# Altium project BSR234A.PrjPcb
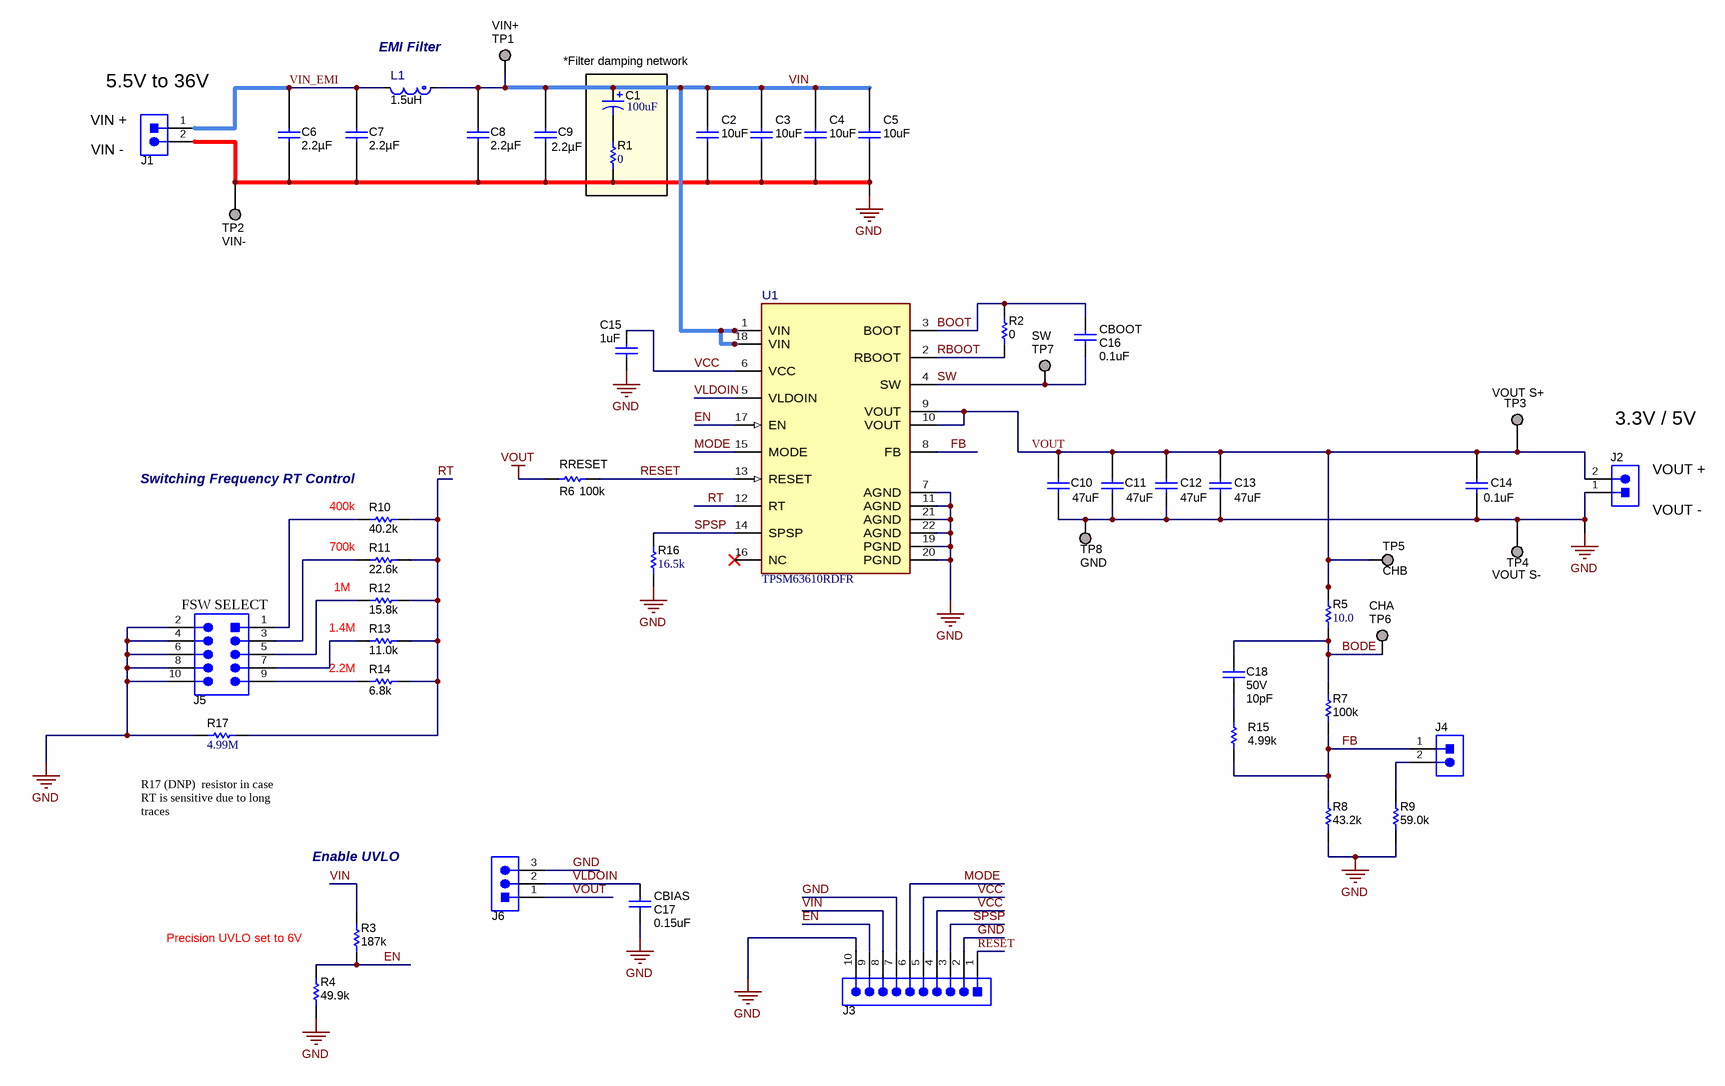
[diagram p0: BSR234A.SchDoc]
CopyrightYear: 2022; PCB_Layout: Jimmy Hua; PCB_Rev: A; PRJ_Customer: Public Release; PRJ_Engineer: Jimmy Hua; PRJ_Number: BSR234; PRJ_Title: VeyronModuleEVM; SCH_Rev: A; TechSupport: http://www.ti.com/support; TID: N/A
2 sheets, 91 parts. Net scope: global (net labels, ports and power ports of the same name join across sheets).
Board file: BSR234A.PcbDoc
Sheets:
  BSR234A.SchDoc
  BSR234A_Hardware.SchDoc

## Sheet BSR234A.SchDoc: TPSM63610 schematic
size 431 x 279 mm; REV: A; Date: Not shown in title block; ApprovedBy: Not shown in title block; CheckedBy: Not shown in title block; Author: Not shown in title block; CompanyName: Not shown in title block; DrawnBy: Jimmy Hua; Engineer: Jimmy Hua; Organization: Not shown in title block; Address1: Not shown in title block; Address2: Not shown in title block; Address3: Not shown in title block; Address4: Not shown in title block; DocumentNumber: 1; Revision: Use project parameter SCH_Rev; SheetNumber: 2; SheetTotal: 2; PageSetup: Record=PageOptions¦CenterHorizontal=True¦CenterVertical=True¦PrintScale=1.00¦XCorrection=1.00¦YCorrection=1.00¦PrintKind=0¦BorderSize=5000000¦LeftOffset=0¦BottomOffset=0¦Orientation=2¦PaperLength=1000¦PaperWidth=1000¦Scale=100¦PaperSource=15¦PrintQuality=600¦MediaType=1¦DitherType=10¦PaperKind=Letter¦PrintScaleMode=1

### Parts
C1  ValueDisplayed: 100uF  [SM_RADIAL_8MM]  (hidden comment: UUD1H101MNL1GS)
C2  ValueDisplayed: 10uF  [1210_270L]  (hidden comment: GRM32ER71H106KA12L)
C3  ValueDisplayed: 10uF  [1210_270L]  (hidden comment: GRM32ER71H106KA12L)
C4  ValueDisplayed: 10uF  [1210_270L]  (hidden comment: GRM32ER71H106KA12L)
C5  ValueDisplayed: 10uF  [1210_270L]  (hidden comment: GRM32ER71H106KA12L)
C6  Cap_F: 2.2µF  [0805L]  (hidden comment: CGA4J3X7R1H225K125AB)
C7  Cap_F: 2.2µF  [0805L]  (hidden comment: CGA4J3X7R1H225K125AB)
C8  Cap_F: 2.2µF  [0805L]  (hidden comment: CGA4J3X7R1H225K125AB)
C9  Cap_F: 2.2µF  [0805L]  (hidden comment: CGA4J3X7R1H225K125AB)
C10  ValueDisplayed: 47uF  [1210_270L]  (hidden comment: GRM32EC81C476ME15L)
C11  ValueDisplayed: 47uF  [1210_270L]  (hidden comment: GRM32EC81C476ME15L)
C12  ValueDisplayed: 47uF  [1210_270L]  (hidden comment: GRM32EC81C476ME15L)
C13  ValueDisplayed: 47uF  [1210_270L]  (hidden comment: GRM32EC81C476ME15L)
C14  ValueDisplayed: 0.1uF  [0603L]  (hidden comment: CGA3E2X7R1E104K080AA)
C15  ValueDisplayed: 1uF  [0603L]  (hidden comment: Capacitor)
C16  CBOOT  ValueDisplayed: 0.1uF  [0402S]
C17  CBIAS  ValueDisplayed: 0.15uF  [0603S]
C18  VDC_V: 50V  ValueDisplayed: 10pF  [0402L]  (hidden comment: CGA2B2C0G1H100D050BA)
J1  1729018  [Phoenix_1729018]  (value not drawn)
J2  1729018  [Phoenix_1729018]  (value not drawn)
J3  TSW-110-07-G-S  [TSW-110-07-G-S]  (value not drawn)
J4  PBC02SAAN  [Sullins_PBC02SAAN]  (value not drawn)
J5  PEC05DAAN  [CONN_PEC05DAAN]  (value not drawn)
J6  PBC03SAAN  [PBC03SAAN]  (value not drawn)
L1  value 1.5uH  [FP-XGL4030-152MEC_SMT2_4MM0_4MM0-MFG]  (hidden comment: XGL4030-152MEC)
R1  ValueDisplayed: 0  [0603L]  (hidden comment: CRCW06030000Z0EA)
R2  ValueDisplayed: 0  [0402S]  (hidden comment: CRCW04020000Z0EDHP)
R3  ValueDisplayed: 187k  [0603]  (hidden comment: CRCW0603187KFKEA)
R4  ValueDisplayed: 49.9k  [0603]  (hidden comment: CRCW060349K9FKEA)
R5  ValueDisplayed: 10.0  [0402L]  (hidden comment: CRCW040210R0FKED)
R6  RRESET  ValueDisplayed: 100k  [0603S]
R7  ValueDisplayed: 100k  [0402S]  (hidden comment: RFBT)
R8  ValueDisplayed: 43.2k  [0402S]  (hidden comment: RFBB)
R9  ValueDisplayed: 59.0k  [0402S]  (hidden comment: RFBB5V)
R10  ValueDisplayed: 40.2k  [0402]  (hidden comment: CRCW040240K2FKED)
R11  ValueDisplayed: 22.6k  [0402]  (hidden comment: CRCW040222K6FKED)
R12  ValueDisplayed: 15.8k  [0402]  (hidden comment: CRCW040215K8FKED)
R13  ValueDisplayed: 11.0k  [0402]  (hidden comment: CRCW040211K0FKED)
R14  ValueDisplayed: 6.8k  [0402]  (hidden comment: CRCW04026K80JNED)
R15  ValueDisplayed: 4.99k  [0402L]  (hidden comment: CRCW04024K99FKED)
R16  ValueDisplayed: 16.5k  [0603S]  (hidden comment: CRCW060316K5FKEA)
R17  ValueDisplayed: 4.99M  [0603]  (hidden comment: CRCW06034M99FKEA)
TP1  VIN+  [Keystone_5019]
TP2  VIN-  [Keystone_5019]
TP3  5019  [Keystone_5019]  (value not drawn)
TP4  5019  [Keystone_5019]  (value not drawn)
TP5  CHB  [Keystone_5019]
TP6  CHA  [Keystone_5019]
TP7  SW  [Keystone_5019]
TP8  GND  [Keystone_5019]
U1  TPSM63610RDFR  [RDF0022A-MFG]

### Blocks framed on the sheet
*Filter damping network: C1 R1

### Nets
GND: C2.1 C3.1 C4.1 C5.1 C6.2 C7.2 C8.2 C9.2 C10.1 C11.1 C12.2 C13.2 C14.2 C15.2 C17.1 J1.2 J2.1 J3.2 J3.7 J3.10 J5.2 J5.4 J5.6 J5.8 J5.10 J6.3 R1.1 R4.1 R8.1 R9.1 R16.1 R17.1 TP2.1 TP4.1 TP8.1 U1.7(AGND) U1.11(AGND) U1.19(PGND) U1.20(PGND) U1.21(AGND) U1.22(AGND)
VOUT: C10.2 C11.2 C12.1 C13.1 C14.1 J2.2 J6.1 R5.2 R6.2 TP3.1 TP5.1 U1.9(VOUT) U1.10(VOUT)
BODE: C18.1 R5.1 R7.2 TP6.1
BOOT: C16.2 R2.2 U1.3(BOOT)
EN: J3.9 R3.2 R4.2 U1.17(EN)
FB: J4.1 R7.1 R8.2 R15.1 U1.8(FB)
MODE: J3.6 U1.15(MODE)
RBOOT: R2.1 U1.2(RBOOT)
RESET: J3.1 R6.1 U1.13(RESET)
RT: R10.2 R11.2 R12.2 R13.2 R14.2 R17.2 U1.12(RT)
SPSP: J3.3 R16.2 U1.14(SPSP)
SW: C16.1 TP7.1 U1.4(SW)
VCC: C15.1 J3.4 J3.5 U1.6(VCC)
VIN: C1.1(+) C2.2 C3.2 C4.2 C5.2 C8.1 C9.1 J3.8 L1.1 R3.1 TP1.1 U1.1(VIN) U1.18(VIN)
VIN_EMI: C6.1 C7.1 J1.1 L1.2
VLDOIN: C17.2 J6.2 U1.5(VLDOIN)
NetC1_2: C1.2(-) R1.2
NetC18_2: C18.2 R15.2
NetJ4_2: J4.2 R9.2
NetJ5_1: J5.1 R10.1
NetJ5_3: J5.3 R11.1
NetJ5_5: J5.5 R12.1
NetJ5_7: J5.7 R13.1
NetJ5_9: J5.9 R14.1

Not connected (* = marked no-connect by the designer): U1 16(NC)*

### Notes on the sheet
- (near J1) 5.5V to 36V
- (near L1) EMI Filter
- (near J1) VIN -
- (near J1) VIN +
- (near TP3) VOUT S+
- (near J2) 3.3V / 5V
- (near R10) Switching Frequency RT Control
- (near R10) 400k
- (near J2) VOUT +
- 700k
- (near TP4) VOUT S-
- (near J2) VOUT -
- (near J5) FSW SELECT
- 1.4M
- 1M
- 2.2M
- (near R17) R17 (DNP)  resistor in case RT is sensitive due to long traces
- Enable UVLO
- Precision UVLO set to 6V

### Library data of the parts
C1 = CMP-0011414-2: CAP, AL, 100 uF, 50 V, +/- 20%, 0.34 ohm, SMD; Manufacturer: Nichicon; TaMin_C: -55°C; ESR_ohm: 0.34; Polarized: Y; SizeAreaWB_mm2: 113.3; U/M: EA; Value: 100uF; TaMax_C: 105°C; SizeZ_mm: 10.2; SizeX_mm: 9; SizeY_mm: 8.3; Cap_Case: 8x10; Value2: 50V; SizeArea_mm2: 74.7; CompType: Capacitor; Cap_F: 100µF; IRMS_A: 300mA; AEC Category: Q200
C2-C5 = CMP-0009226-3: CAP, CERM, 10 uF, 50 V, +/- 10%, X7R, 1210; Manufacturer: MuRata; TaMin_C: -55°C; Polarized: N; SizeAreaWB_mm2: 14.7; Value1: Unknown; U/M: EA; Value: 10uF; TaMax_C: 125°C; SizeZ_mm: 2.7; SizeX_mm: 3.2; SizeY_mm: 2.5; Cap_Case: 1210; Value2: 50V; SizeArea_mm2: 8; Cap_F: 10µF; AEC Category: Q200
C6-C9 = CMP-0007977-2: CAP, CERM, 2.2 uF, 50 V, +/- 10%, X7R, AEC-Q200 Grade 1, 0805; Manufacturer: TDK; TaMin_C: -55°C; ESR_ohm: 3.288m; Polarized: N; SizeAreaWB_mm2: 6.75; Value1: 0.003288 ohm; U/M: EA; Value: 2.2uF; TaMax_C: 125°C; SizeZ_mm: 1.45; SizeX_mm: 2; SizeY_mm: 1.25; Cap_Case: 0805; Value2: 50V; SizeArea_mm2: 2.5; AEC Qualified: Y; IRMS_A: 3.60029A; AEC Grade: 1; AEC Category: Q200
C10-C13 = CMP-0009201-2: CAP, CERM, 47 uF, 16 V, +/- 20%, X6S, 1210; Manufacturer: MuRata; TaMin_C: -55°C; Polarized: N; SizeAreaWB_mm2: 14.7; Value1: Unknown; U/M: EA; Value: 47uF; TaMax_C: 105°C; SizeZ_mm: 2.7; SizeX_mm: 3.2; SizeY_mm: 2.5; Cap_Case: 1210; Value2: 16V; SizeArea_mm2: 8; Cap_F: 47µF; AEC Category: Q200
C14 = CMP-0007077-5: CAP, CERM, 0.1 uF, 25 V, +/- 10%, X7R, AEC-Q200 Grade 1, 0603; Manufacturer: TDK; TaMin_C: -55°C; Polarized: N; SizeAreaWB_mm2: 4.68; Value1: Unknown; U/M: EA; Value: 0.1uF; TaMax_C: 125°C; SizeZ_mm: 1; SizeX_mm: 1.6; SizeY_mm: 0.8; Cap_Case: 0603; Value2: 25V; SizeArea_mm2: 1.28; AEC Qualified: Y; Cap_F: 100nF; AEC Category: Q200
C15 = CMP-0006867-4: CAP, CERM, 1 uF, 25 V, +/- 10%, X7R, 0603; PartNumber: C0603C105K3RACTU; Manufacturer: Kemet; Polarized: N; Value: 1uF; U/M: EA; Cap_F: 1µF; Value1: Unknown; VDC_V: 25V; TaMin_C: -55°C; TaMax_C: 125°C; Cap_Case: 0603; AEC Category: Q200; SizeArea_mm2: 1.28; SizeAreaWB_mm2: 4.68; SizeX_mm: 1.6; SizeY_mm: 0.8; SizeZ_mm: 1
C16 = CMP-0006325-2: CAP, CERM, 0.1 uF, 50 V, +/- 10%, X7R, AEC-Q200 Grade 1, 0402; Manufacturer: TDK; PartNumber: CGA2B3X7R1H104K050BB; TaMin_C: -55°C; ESR_ohm: 0.039064; Polarized: N; SizeAreaWB_mm2: 3; Value1: 0.039064 ohm; U/M: EA; Value: 0.1uF; TaMax_C: 125°C; SizeZ_mm: 0.6; SizeX_mm: 1; SizeY_mm: 0.5; Cap_Case: 0402; Value2: 50V; CompType: Capacitor; AEC Qualified: Y; Cap_F: 100nF; IRMS_A: 8.14669dA; AEC Category: Q200
C17 = CMP-0007093-5: CAP, CERM, 0.15 uF, 50 V, +/- 10%, X7R, AEC-Q200 Grade 1, 0603; Manufacturer: TDK; PartNumber: CGA3E3X7R1H154K080AB; TaMin_C: -55°C; ESR_ohm: 0.028863; Polarized: N; SizeAreaWB_mm2: 4.68; Value1: 0.028863 ohm; U/M: EA; Value: 0.15uF; TaMax_C: 125°C; SizeZ_mm: 1; SizeX_mm: 1.6; SizeY_mm: 0.8; Cap_Case: 0603; Value2: 50V; SizeArea_mm2: 1.28; CompType: Capacitor; AEC Qualified: Y; Cap_F: 150nF; IRMS_A: 9.78809dA; AEC Category: Q200
C18 = CMP-0006307-2: CAP, CERM, 10 pF, 50 V, +/- 5%, C0G/NP0, AEC-Q200 Grade 1, 0402; Manufacturer: TDK; TaMin_C: -55°C; Polarized: N; SizeAreaWB_mm2: 3; Value1: Unknown; U/M: EA; Value: 10pF; TaMax_C: 125°C; SizeZ_mm: 0.6; SizeX_mm: 1; SizeY_mm: 0.5; Cap_Case: 0402; CompType: Capacitor; AEC Qualified: Y; AEC Category: Q200
J1 J2 = CMP-0055486-1: TERM BLOCK 2POS 5mm, TH; Manufacturer: Phoenix Contact; CT: TRUE; Green_REACh: Incomplete; CompType: Terminal Block; CNHeader: FALSE; Green_Lifecycle: Not Set
J3 = CMP-0075422-1: Header, 100mil, 10x1, Gold, TH; Manufacturer: Samtec; Pitch_mm: 2.54; Cert_VDE: N; Gender: Male; Cert_CSA: Y; Voltage_V: 550V; Green_REACh: Passed; Current_A: 6.3A; CT: False; Green_Lifecycle: Active; Row_Count: 1; CNHeader: True
J4 = CMP-0054566-1: Header, 100mil, 2x1, Gold, TH; Manufacturer: Sullins Connector Solutions; CNHeader: TRUE; Current_A: 3A; Green_Lifecycle: Active; Shrouded: N; Gender: Male; Green_REACh: Passed; Voltage_V: 1.8kV; Row_Count: 1; Pitch_mm: 2.54; CT: FALSE; Cert_UL: Y
J5 = CMP-0054550-2: Header, 100mil, 5x2, Tin, TH; Manufacturer: Sullins Connector Solutions; Pitch_mm: 2.54; Gender: Male; Cert_UL: Y; Voltage_V: 1.8kV; Green_REACh: Passed; Current_A: 3A; Shrouded: N; Green_Lifecycle: Active; Row_Count: 2
J6 = CMP-0002334-1: Header, 100mil, 3x1, Gold, TH; Manufacturer: Sullins Connector Solutions; CNHeader: TRUE; CT: FALSE; Green_Lifecycle: Not Set; Green_REACh: Incomplete
L1 = CMP-0092596-1: Shielded Power Inductors 1.5 µH 10.2A 10.5mOhm Max Nonstandard; Manufacturer: Coilcraft; Isat: 3.8A; Tolerance_%: 20%; AEC Grade: Grade 1; Self Resonant Frequency: 50MHz; TaMin_C: -40°C; Test Frequency: 1MHz; Material: Composite; DCR_ohm: 0.0105; TaMax_C: +125°C; AEC Qualified: Yes; SizeZ_mm: 3.1mm; Ind_H: 1.5µH; Shrouded: true
R1 = CMP-0025697-4: RES, 0, 5%, 0.1 W, AEC-Q200 Grade 0, 0603; Manufacturer: Vishay-Dale; Power_W: 100mW; TempCo: 200 ppm/C; Value_Code: 0000; Value: 0; EIA_Code: E24; SizeX_mm: 1.6; SizeY_mm: 0.8; SizeZ_mm: 1; Value2: 0.1W; SizeArea_mm2: 1.28; AEC Qualified: Y; VDC_V: 75V; AEC Category: Q200
R2 = CMP-0081856-1: RES, 0, 0%, 0.2 W, AEC-Q200 Grade 0, 0402; Manufacturer: Vishay-Dale; SizeAreaWB_mm2: 3; SizeArea_mm2: 0.5; AEC Qualified: Y; AEC Category: Q200; Value: 0; SizeZ_mm: 0.6; Power_W: 200mW; VDC_V: 50V; Value2: 0.2W; SizeX_mm: 1
R3 = CMP-0022095-4: RES, 187 k, 1%, 0.1 W, AEC-Q200 Grade 0, 0603; Manufacturer: Vishay-Dale; Power_W: 100mW; TempCo: 100 ppm/C; Value: 187k; EIA_Code: E96; SizeX_mm: 1.6; SizeY_mm: 0.8; SizeZ_mm: 1; Value2: 0.1W; SizeArea_mm2: 1.28; AEC Qualified: Y; VDC_V: 75V; AEC Category: Q200; AEC Grade: 0
R4 = CMP-0022447-4: RES, 49.9 k, 1%, 0.1 W, AEC-Q200 Grade 0, 0603; Manufacturer: Vishay-Dale; Power_W: 100mW; TempCo: 100 ppm/C; Value_Code: 49k9; Value: 49.9k; EIA_Code: E96; SizeX_mm: 1.6; SizeY_mm: 0.8; SizeZ_mm: 1; Value2: 0.1W; SizeArea_mm2: 1.28; AEC Qualified: Y; VDC_V: 75V; AEC Category: Q200; AEC Grade: 0
R5 = CMP-0025963-1: RES, 10.0, 1%, 0.063 W, 0402; Manufacturer: Vishay-Dale; Power_W: 63mW; TempCo: 100 ppm/C; Value_Code: 10R0; U/M: EA; Value: 10.0; EIA_Code: E96; Res_ohm: 10; SizeX_mm: 1; SizeY_mm: 0.5; SizeZ_mm: 0.6; Value2: 0.063W; VDC_V: 50V; AEC Category: Q200
R6 = CMP-0021990-4: RES, 100 k, 1%, 0.1 W, AEC-Q200 Grade 0, 0603; Manufacturer: Vishay-Dale; PartNumber: CRCW0603100KFKEA; Power_W: 100mW; TempCo: 100 ppm/C; Value: 100k; EIA_Code: E96; SizeX_mm: 1.6; SizeY_mm: 0.8; SizeZ_mm: 1; Value2: 0.1W; SizeArea_mm2: 1.28; CompType: Resistor; AEC Qualified: Y; VDC_V: 75V; AEC Category: Q200; AEC Grade: 0
R7 = CMP-0025950-3: RES, 100 k, 1%, 0.063 W, AEC-Q200 Grade 0, 0402; Manufacturer: Vishay-Dale; PartNumber: CRCW0402100KFKED; Power_W: 63mW; TempCo: 100 ppm/C; Value: 100k; EIA_Code: E96; SizeX_mm: 1; SizeY_mm: 0.5; SizeZ_mm: 0.6; Value2: 0.063W; CompType: Resistor; AEC Qualified: Y; VDC_V: 50V; AEC Category: Q200; AEC Grade: 0
R8 = CMP-0026379-2: RES, 43.2 k, 1%, 0.063 W, AEC-Q200 Grade 0, 0402; Manufacturer: Vishay-Dale; PartNumber: CRCW040243K2FKED; Power_W: 63mW; TempCo: 100 ppm/C; Value_Code: 43k2; Value: 43.2k; EIA_Code: E96; SizeX_mm: 1; SizeY_mm: 0.5; SizeZ_mm: 0.6; Value2: 0.063W; CompType: Resistor; AEC Qualified: Y; VDC_V: 50V; AEC Category: Q200; AEC Grade: 0
R9 = CMP-0026461-2: RES, 59.0 k, 1%, 0.063 W, AEC-Q200 Grade 0, 0402; Manufacturer: Vishay-Dale; PartNumber: CRCW040259K0FKED; Power_W: 63mW; TempCo: 100 ppm/C; Value_Code: 59k0; Value: 59.0k; EIA_Code: E96; Res_ohm: 59k; SizeX_mm: 1; SizeY_mm: 0.5; SizeZ_mm: 0.6; Value2: 0.063W; CompType: Resistor; AEC Qualified: Y; VDC_V: 50V; AEC Category: Q200; AEC Grade: 0
R10 = CMP-0026367-2: RES, 40.2 k, 1%, 0.063 W, AEC-Q200 Grade 0, 0402; Manufacturer: Vishay-Dale; Power_W: 63mW; TempCo: 100 ppm/C; Value_Code: 40k2; Value: 40.2k; EIA_Code: E96; SizeX_mm: 1; SizeY_mm: 0.5; SizeZ_mm: 0.6; Value2: 0.063W; AEC Qualified: Y; VDC_V: 50V; AEC Category: Q200; AEC Grade: 0
R11 = CMP-0026179-2: RES, 22.6 k, 1%, 0.063 W, AEC-Q200 Grade 0, 0402; Manufacturer: Vishay-Dale; Power_W: 63mW; TempCo: 100 ppm/C; Value_Code: 22k6; Value: 22.6k; EIA_Code: E96; SizeX_mm: 1; SizeY_mm: 0.5; SizeZ_mm: 0.6; Value2: 0.063W; AEC Qualified: Y; VDC_V: 50V; AEC Category: Q200; AEC Grade: 0
R12 = CMP-0026029-3: RES, 15.8 k, 1%, 0.063 W, AEC-Q200 Grade 0, 0402; Manufacturer: Vishay-Dale; Power_W: 63mW; TempCo: 100 ppm/C; Value_Code: 15k8; Value: 15.8k; EIA_Code: E96; SizeX_mm: 1; SizeY_mm: 0.5; SizeZ_mm: 0.6; Value2: 0.063W; AEC Qualified: Y; VDC_V: 50V; AEC Category: Q200; AEC Grade: 0
R13 = CMP-0025975-2: RES, 11.0 k, 1%, 0.063 W, 0402; Manufacturer: Vishay-Dale; Power_W: 63mW; TempCo: 100 ppm/C; Value_Code: 11k0; U/M: EA; Value: 11.0k; EIA_Code: E96; Res_ohm: 11k; SizeX_mm: 1; SizeY_mm: 0.5; SizeZ_mm: 0.6; Value2: 0.063W; VDC_V: 50V; AEC Category: Q200
R14 = CMP-0026966-5: RES, 6.8 k, 5%, 0.063 W, AEC-Q200 Grade 0, 0402; Manufacturer: Vishay-Dale; Power_W: 63mW; TempCo: 200 ppm/C; Value_Code: 6k80; Value: 6.8k; EIA_Code: E24; SizeX_mm: 1; SizeY_mm: 0.5; SizeZ_mm: 0.6; Value2: 0.063W; AEC Qualified: Y; VDC_V: 50V; AEC Category: Q200; AEC Grade: 0
R15 = CMP-0026414-2: RES, 4.99 k, 1%, 0.063 W, AEC-Q200 Grade 0, 0402; Manufacturer: Vishay-Dale; Power_W: 63mW; TempCo: 100 ppm/C; Value_Code: 4k99; Value: 4.99k; EIA_Code: E96; SizeX_mm: 1; SizeY_mm: 0.5; SizeZ_mm: 0.6; Value2: 0.063W; CompType: Resistor; AEC Qualified: Y; VDC_V: 50V; AEC Category: Q200; AEC Grade: 0
R16 = CMP-0022080-4: RES, 16.5 k, 1%, 0.1 W, AEC-Q200 Grade 0, 0603; Manufacturer: Vishay-Dale; Power_W: 100mW; TempCo: 100 ppm/C; Value_Code: 16k5; Value: 16.5k; EIA_Code: E96; SizeX_mm: 1.6; SizeY_mm: 0.8; SizeZ_mm: 1; Value2: 0.1W; SizeArea_mm2: 1.28; AEC Qualified: Y; VDC_V: 75V; AEC Category: Q200; AEC Grade: 0
R17 = CMP-0022468-4: RES, 4.99 M, 1%, 0.1 W, AEC-Q200 Grade 0, 0603; Manufacturer: Vishay-Dale; Power_W: 100mW; TempCo: 100 ppm/C; Value_Code: 4M99; Value: 4.99Meg; EIA_Code: E96; SizeX_mm: 1.6; SizeY_mm: 0.8; SizeZ_mm: 1; Value2: 0.1W; SizeArea_mm2: 1.28; AEC Qualified: Y; VDC_V: 75V; AEC Category: Q200; AEC Grade: 0
TP1 TP2 TP5-TP8 = CMP-0055162-1: Test Point, Miniature, SMT; Manufacturer: Keystone; PartNumber: 5019; CNHeader: FALSE; Green_Lifecycle: Active; Green_REACh: Passed; CT: TRUE
TP3 TP4 = CMP-0055162-1: Test Point, Miniature, SMT; Manufacturer: Keystone; CNHeader: FALSE; Green_Lifecycle: Active; Green_REACh: Passed; CT: TRUE
U1 = CMP-0095755-2: Manufacturer: Texas Instruments; CompType: IC; AEC Category: Q200; SizeZ_mm: 4.05mm

## Sheet BSR234A_Hardware.SchDoc: TPSM63610
size 431 x 279 mm; Date: Not shown in title block; ApprovedBy: Not shown in title block; CheckedBy: Not shown in title block; Author: Not shown in title block; CompanyName: Not shown in title block; DrawnBy: Jimmy Hua; Engineer: Not shown in title block; Organization: Not shown in title block; Address1: Not shown in title block; Address2: Not shown in title block; Address3: Not shown in title block; Address4: Not shown in title block; DocumentNumber: 1; Revision: Use project parameter SCH_Rev; SheetNumber: 1; SheetTotal: 2; PageSetup: Record=PageOptions¦CenterHorizontal=True¦CenterVertical=True¦PrintScale=1.00¦XCorrection=1.00¦YCorrection=1.00¦PrintKind=0¦BorderSize=5000000¦LeftOffset=0¦BottomOffset=0¦Orientation=2¦PaperLength=1000¦PaperWidth=1000¦Scale=100¦PaperSource=15¦PrintQuality=600¦MediaType=1¦DitherType=10¦PaperKind=Letter¦PrintScaleMode=1
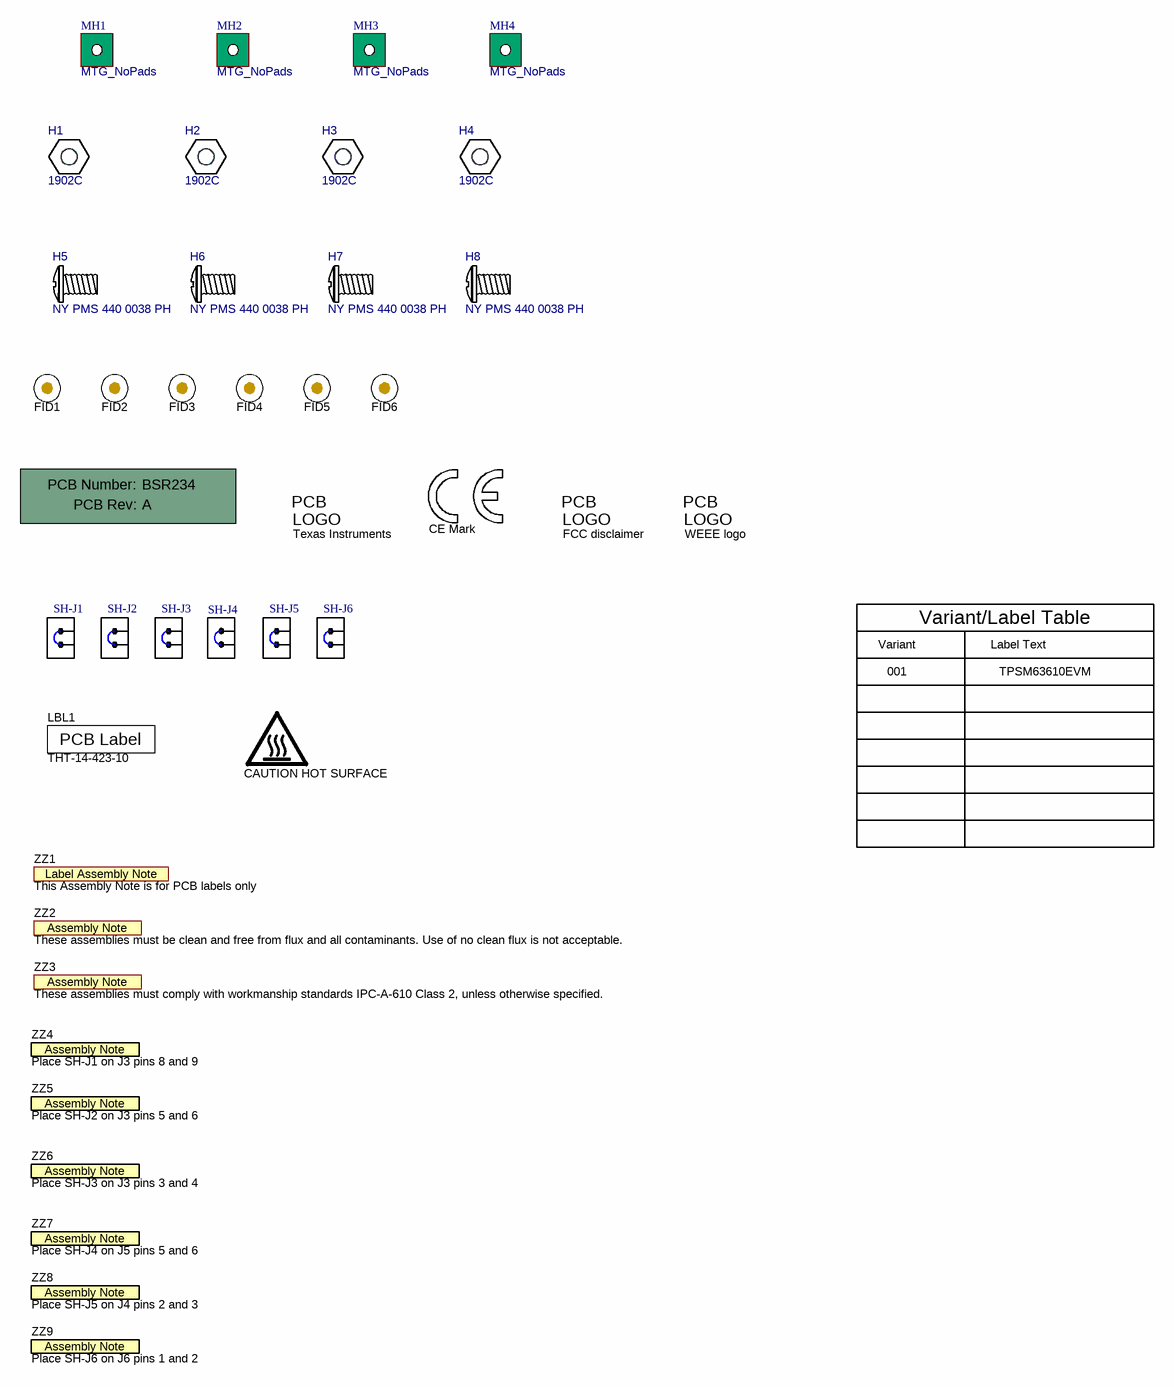
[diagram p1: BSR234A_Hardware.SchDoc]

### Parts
!PCB1  Printed Circuit Board  (value not drawn)  (mechanical)
FID1  Fiducial  [Fiducial10-20]  (value not drawn)
FID2  Fiducial  [Fiducial10-20]  (value not drawn)
FID3  Fiducial  [Fiducial10-20]  (value not drawn)
FID4  Fiducial  [Fiducial10-20]  (value not drawn)
FID5  Fiducial  [Fiducial10-20]  (value not drawn)
FID6  Fiducial  [Fiducial10-20]  (value not drawn)
H1  1902C  [Keystone_1902C]  (mechanical)
H2  1902C  [Keystone_1902C]  (mechanical)
H3  1902C  [Keystone_1902C]  (mechanical)
H4  1902C  [Keystone_1902C]  (mechanical)
H5  NY PMS 440 0038 PH  (mechanical)
H6  NY PMS 440 0038 PH  (mechanical)
H7  NY PMS 440 0038 PH  (mechanical)
H8  NY PMS 440 0038 PH  (mechanical)
LBL1  THT-14-423-10  [Label_650x200]
Logo1  CE Mark  [CE_Mark_5mm]  (no BOM)
Logo2  Texas Instruments  [TI_Stacked_Overlay_Small]  (no BOM)
Logo3  FCC disclaimer  [FCC_disclaimer]  (no BOM)
Logo4  WEEE logo  [WEEE_Minimum]  (no BOM)
LOGO5  CAUTION HOT SURFACE  [IEC_HotSurface_Small]  (no BOM)
MH1  MTG_NoPads  [MTG_159mil]  (no BOM)
MH2  MTG_NoPads  [MTG_159mil]  (no BOM)
MH3  MTG_NoPads  [MTG_159mil]  (no BOM)
MH4  MTG_NoPads  [MTG_159mil]  (no BOM)
SH-J1  SNT-100-BK-G  [SNT-100-BK-G]  (value not drawn)
SH-J2  SNT-100-BK-G  [SNT-100-BK-G]  (value not drawn)
SH-J3  SNT-100-BK-G  [SNT-100-BK-G]  (value not drawn)
SH-J4  SNT-100-BK-G  [SNT-100-BK-G]  (value not drawn)
SH-J5  SNT-100-BK-G  [SNT-100-BK-G]  (value not drawn)
SH-J6  SNT-100-BK-G  [SNT-100-BK-G]  (value not drawn)
ZZ1  This Assembly Note is for PCB labels only  [AssemblyNoteLabel]  (no BOM)
ZZ2  These assemblies must be clean and free from flux and all contaminants. Use of no clean flux is not acceptable.  [AssemblyNote]  (no BOM)
ZZ3  These assemblies must comply with workmanship standards IPC-A-610 Class 2, unless otherwise specified.  [AssemblyNote]  (no BOM)
ZZ4  Place SH-J1 on J3 pins 8 and 9  [AssemblyNote]  (no BOM)
ZZ5  Place SH-J2 on J3 pins 5 and 6  [AssemblyNote]  (no BOM)
ZZ6  Place SH-J3 on J3 pins 3 and 4  [AssemblyNote]  (no BOM)
ZZ7  Place SH-J4 on J5 pins 5 and 6  [AssemblyNote]  (no BOM)
ZZ8  Place SH-J5 on J4 pins 2 and 3  [AssemblyNote]  (no BOM)
ZZ9  Place SH-J6 on J6 pins 1 and 2  [AssemblyNote]  (no BOM)

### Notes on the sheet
- Variant/Label Table
- Variant
- 001
- Label Text
- TPSM63610EVM

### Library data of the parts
!PCB1 = CMP-0003618-2: Manufacturer: Any; PartNumber: BSR234
FID1-FID6 = CMP-0077181-1: Fiducial mark.  There is nothing to buy or mount.
H1-H4 = CMP-0003610-1: Standoff, Hex, 0.5"L #4-40 Nylon; Manufacturer: Keystone; CompType: Hardware
H5-H8 = CMP-0003667-1: Screw, Pan Head , 4-40, 3/8", Nylon; Manufacturer: B&F Fastener Supply; CompType: Hardware
LBL1 = CMP-0003625-1: Manufacturer: Brady
Logo1 = CMP-0074844-1: SymbolCreator: a0412235
Logo2 = CMP-0074838-1: Texas Instrument Corporate Signature; SymbolCreator: a0412235; Lib Reference: TI_Logo; Library Reference: Logo
Logo3 = CMP-0074847-1: FCC_disclaimer
Logo4 = CMP-0074769-1
LOGO5 = CMP-0074837-1: IEC 61010-1 Hot Surface Warning; SymbolCreator: a0412235
MH1-MH4 = CMP-0078424-2: PCB Mounting Hole, No Pad; Manufacturer: Any; Key: Mounting Hole (non-standard) No Pad
SH-J1-SH-J6 = CMP-0003623-3: Shunt, 100mil, Gold plated, Black; Alternate PartNumber: 969102-0000-DA; Manufacturer: Samtec; Alternate Manufacturer: 3M; Value: 1x2; Note: You can "mate" this to a header by matching the designator.  i.e. use SH-J3 for header J3
ZZ1 = CMP-0003616-3
ZZ2 = CMP-0077237-1
ZZ3 = CMP-0077238-1
ZZ4-ZZ9 = CMP-0003615-1: This Assembly Note will show in the PcbDoc and associated outputs

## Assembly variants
001: not fitted C16 C18 R15 R17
